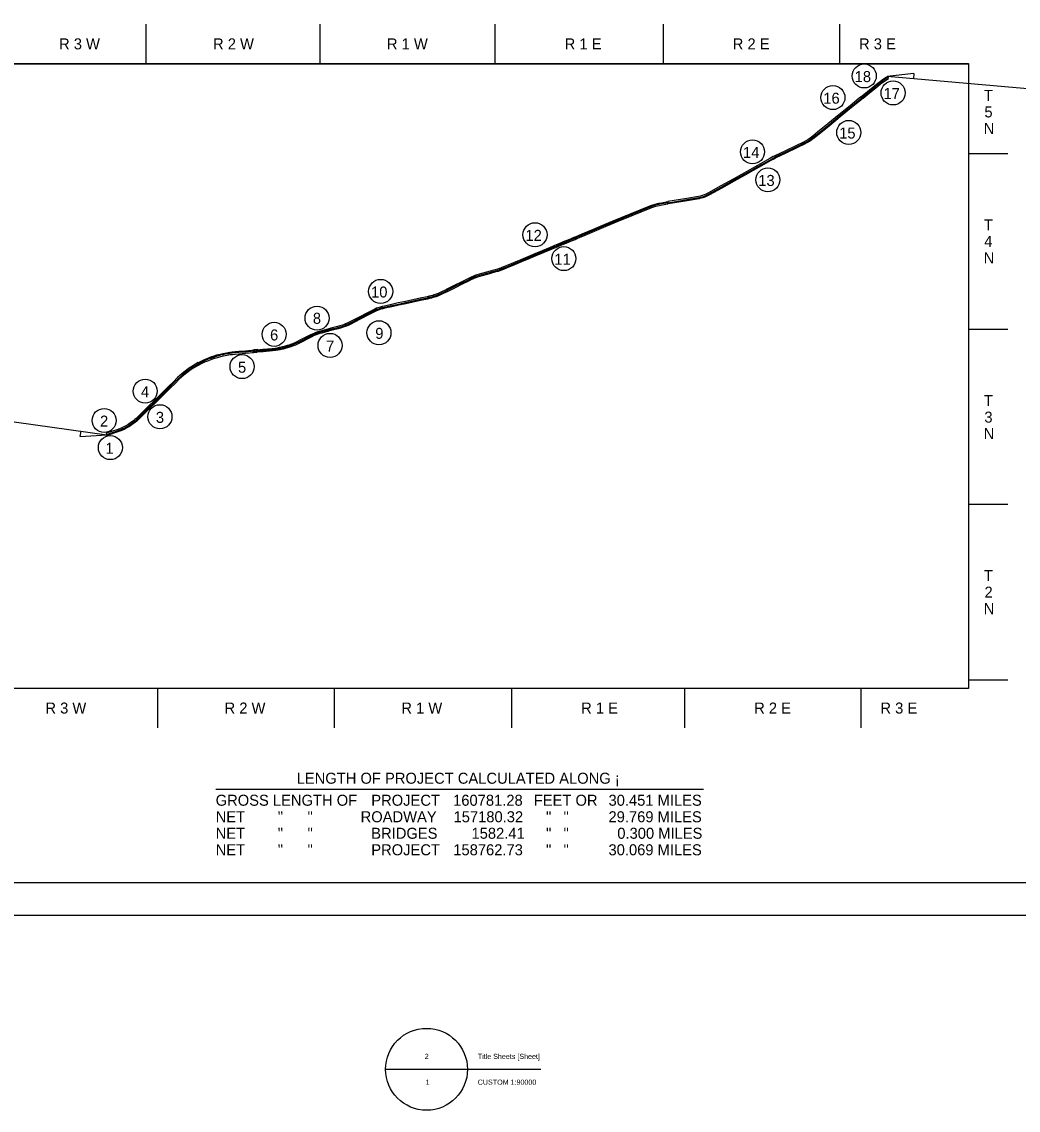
# Model space of a CAD drawing. Extents: x -0.96 to 2.36, y -0.12 to 0.92.
# Drawn here: x 0.451 to 1.084, y -0.124 to 0.568 of the extents above; entities that cross this region are included whole.
import ezdxf

# ---------------------------------------------------------------- set-up
doc = ezdxf.new("R2010")
doc.units = 0
for name, color, linetype in [('Default', 7, 'Continuous'), ('DSN_DRFT_DNC', 7, 'Continuous'), ('Level 41', 7, 'Continuous'), ('Level 57', 7, 'Continuous'), ('SHET_Annotations', 7, 'Continuous'), ('SHET_Border-Lines', 7, 'Continuous'), ('SHET_Border-Text', 7, 'Continuous')]:
    doc.layers.add(name, color=color, linetype=linetype)

msp = doc.modelspace()

# ---------------------------------------------------------------- linework, layer by layer
at = {"layer": 'Default'}
for p, q in [((0.68206, -0.09792), (0.73415, -0.09792)), ((0.70833, -0.09792), (0.78086, -0.09792))]:
    msp.add_line(p, q, dxfattribs=at)
msp.add_circle((0.70811, -0.09792), 0.02604, dxfattribs=at)
at = {"layer": 'DSN_DRFT_DNC'}
msp.add_lwpolyline([(0.4056, 0.54167), (1.05273, 0.54167), (1.05273, 0.1443), (0.4056, 0.1443)], close=True, dxfattribs=at)
at = {"layer": 'Level 41'}
msp.add_lwpolyline([(0.4056, 0.54158), (1.05273, 0.54158), (1.05273, 0.14421), (0.4056, 0.14421)], close=True, dxfattribs=at)
at = {"layer": 'Level 57'}
msp.add_line((0.83298, 0.44301), (0.83297, 0.44301), dxfattribs=at)
for points in [[(0.98504, 0.51997), (0.98418, 0.5203), (0.98863, 0.52394), (0.99421, 0.52849), (0.99591, 0.52987), (0.99871, 0.53192), (1.00046, 0.53302), (1.00124, 0.53346), (1.00164, 0.53276), (1.00087, 0.53233), (0.99916, 0.53125), (0.9964, 0.52923), (0.99472, 0.52787), (0.98913, 0.52332)], [(1.00192, 0.53213), (1.00159, 0.53272), (1.00088, 0.53232), (0.99917, 0.53124), (0.99641, 0.52922), (0.99473, 0.52786), (0.98914, 0.52331), (0.98512, 0.52001), (0.98546, 0.51988), (0.98585, 0.51975), (0.98957, 0.52279), (0.99515, 0.52734), (0.99682, 0.52869), (0.99954, 0.53069), (1.00122, 0.53174)], [(0.96384, 0.50267), (0.9708, 0.50833), (0.97801, 0.51422), (0.98378, 0.51893), (0.98503, 0.51995), (0.98416, 0.52029), (0.98327, 0.51955), (0.9775, 0.51484), (0.97029, 0.50896), (0.96333, 0.50329), (0.95678, 0.49794), (0.9538, 0.49553), (0.95385, 0.49453), (0.95729, 0.49732)], [(0.97081, 0.50832), (0.97802, 0.51421), (0.98379, 0.51892), (0.98498, 0.5199), (0.9857, 0.51962), (0.98421, 0.5184), (0.97844, 0.51369), (0.97123, 0.5078), (0.96427, 0.50214), (0.95772, 0.49679), (0.95463, 0.49429), (0.95394, 0.49379), (0.95391, 0.49459), (0.95423, 0.49482), (0.9573, 0.49731), (0.96385, 0.50266)], [(0.89554, 0.46311), (0.9034, 0.46747), (0.91068, 0.47153), (0.91897, 0.47617), (0.92674, 0.4805), (0.929, 0.48178), (0.92991, 0.48224), (0.93631, 0.48531), (0.94378, 0.48887), (0.94809, 0.49093), (0.9497, 0.49183), (0.95092, 0.49256), (0.9525, 0.4936), (0.95382, 0.49456), (0.95378, 0.49549), (0.95205, 0.49424), (0.9505, 0.49322), (0.94931, 0.49251), (0.94773, 0.49162), (0.94344, 0.48957), (0.93597, 0.48602), (0.92956, 0.48295), (0.92863, 0.48247), (0.92636, 0.48119), (0.91859, 0.47686), (0.91029, 0.47221), (0.90302, 0.46816), (0.89516, 0.46379), (0.88738, 0.45946), (0.88581, 0.45865), (0.88456, 0.45812), (0.88346, 0.45774), (0.88221, 0.4574), (0.88112, 0.45718), (0.87353, 0.45588), (0.8655, 0.45453), (0.86159, 0.45386), (0.86162, 0.45308), (0.86563, 0.45376), (0.87366, 0.45511), (0.88126, 0.45641), (0.88239, 0.45663), (0.88369, 0.45699), (0.88484, 0.45739), (0.88614, 0.45794), (0.88775, 0.45877)], [(0.91101, 0.47092), (0.90374, 0.46687), (0.89588, 0.4625), (0.88808, 0.45816), (0.88644, 0.45731), (0.88509, 0.45674), (0.8839, 0.45633), (0.88255, 0.45596), (0.88138, 0.45573), (0.87377, 0.45443), (0.86574, 0.45307), (0.86171, 0.45239), (0.86168, 0.45306), (0.86563, 0.45373), (0.87366, 0.45509), (0.88126, 0.45639), (0.88239, 0.45661), (0.8837, 0.45696), (0.88485, 0.45737), (0.88615, 0.45791), (0.88776, 0.45875), (0.89555, 0.46308), (0.90342, 0.46745), (0.91069, 0.47151), (0.91899, 0.47615), (0.92675, 0.48048), (0.92901, 0.48176), (0.92992, 0.48222), (0.93632, 0.48529), (0.94379, 0.48884), (0.9481, 0.49091), (0.94971, 0.49181), (0.95093, 0.49254), (0.95251, 0.49358), (0.95377, 0.49449), (0.95379, 0.49368), (0.95289, 0.49303), (0.95129, 0.49197), (0.95004, 0.49123), (0.9484, 0.49031), (0.94407, 0.48824), (0.93661, 0.48469), (0.93022, 0.48162), (0.92933, 0.48117), (0.92708, 0.4799), (0.91931, 0.47557)], [(0.85145, 0.45165), (0.85352, 0.45229), (0.85573, 0.45283), (0.85758, 0.45318), (0.86155, 0.45385), (0.86158, 0.45307), (0.85771, 0.45241), (0.8559, 0.45207), (0.85373, 0.45154), (0.85169, 0.45091), (0.85003, 0.45034), (0.83285, 0.4433), (0.82964, 0.44196), (0.82209, 0.4388), (0.81462, 0.43566), (0.80732, 0.43261), (0.80349, 0.431), (0.80232, 0.43051), (0.80126, 0.43007), (0.80008, 0.42957), (0.79665, 0.42815), (0.79324, 0.42671), (0.79001, 0.42537), (0.7888, 0.42485), (0.78878, 0.42541), (0.78877, 0.42568), (0.78971, 0.42608), (0.79294, 0.42743), (0.79635, 0.42886), (0.79978, 0.43028), (0.80096, 0.43078), (0.80202, 0.43122), (0.80318, 0.43172), (0.80702, 0.43332), (0.81432, 0.43638), (0.82178, 0.43951), (0.82934, 0.44268), (0.83255, 0.44402), (0.83256, 0.44402), (0.84976, 0.45107)], [(0.76368, 0.41436), (0.76824, 0.41627), (0.77283, 0.41819), (0.77728, 0.42006), (0.78197, 0.422), (0.78707, 0.42415), (0.78876, 0.42486), (0.78879, 0.42403), (0.78738, 0.42343), (0.78227, 0.42129), (0.77758, 0.41934), (0.77314, 0.41747), (0.76854, 0.41555), (0.76398, 0.41364), (0.75939, 0.41171), (0.75651, 0.41051), (0.75519, 0.41003), (0.75517, 0.41085), (0.75622, 0.41123), (0.75908, 0.41243)], [(0.76367, 0.41439), (0.76822, 0.4163), (0.77282, 0.41822), (0.77727, 0.42009), (0.78196, 0.42203), (0.78706, 0.42418), (0.7887, 0.42487), (0.78867, 0.42558), (0.78681, 0.42478), (0.78171, 0.42264), (0.77702, 0.42069), (0.77257, 0.41883), (0.76797, 0.41691), (0.76341, 0.41499), (0.75882, 0.41307), (0.75597, 0.41188), (0.7552, 0.4116), (0.75523, 0.41091), (0.75621, 0.41126), (0.75907, 0.41246)], [(0.71121, 0.39248), (0.71006, 0.39219), (0.7088, 0.39191), (0.70433, 0.39093), (0.6997, 0.38993), (0.695, 0.38891), (0.69048, 0.38793), (0.68609, 0.38698), (0.6816, 0.386), (0.6802, 0.38568), (0.67912, 0.3854), (0.67839, 0.38516), (0.67684, 0.38461), (0.67584, 0.38418), (0.67499, 0.38377), (0.67377, 0.38314), (0.67167, 0.38204), (0.66549, 0.37881), (0.66004, 0.37598), (0.65875, 0.37537), (0.65714, 0.37471), (0.65636, 0.3744), (0.65511, 0.37397), (0.65337, 0.37343), (0.65181, 0.37301), (0.64833, 0.37218), (0.64569, 0.37153), (0.64565, 0.37236), (0.64814, 0.37297), (0.65161, 0.3738), (0.65314, 0.37421), (0.65486, 0.37474), (0.65608, 0.37516), (0.65683, 0.37547), (0.65842, 0.37611), (0.65968, 0.37671), (0.66511, 0.37953), (0.67129, 0.38276), (0.6734, 0.38386), (0.67462, 0.3845), (0.6755, 0.38492), (0.67654, 0.38537), (0.67813, 0.38594), (0.6789, 0.38618), (0.68, 0.38647), (0.68142, 0.3868), (0.68592, 0.38778), (0.6903, 0.38873), (0.69483, 0.3897), (0.69953, 0.39073), (0.70415, 0.39172), (0.70862, 0.3927), (0.70987, 0.39298), (0.711, 0.39326), (0.7121, 0.39357), (0.71295, 0.39385), (0.71391, 0.39417), (0.71575, 0.39487), (0.71714, 0.39547), (0.7184, 0.39606), (0.71985, 0.39678), (0.72123, 0.39747), (0.72596, 0.39982), (0.73039, 0.40204), (0.73433, 0.404), (0.73632, 0.40498), (0.73717, 0.40538), (0.73789, 0.4057), (0.73912, 0.4062), (0.74033, 0.40664), (0.74173, 0.40711), (0.74316, 0.40754), (0.74643, 0.4084), (0.74796, 0.4088), (0.752, 0.40988), (0.75336, 0.41027), (0.7545, 0.41063), (0.75514, 0.41086), (0.75517, 0.41001), (0.75477, 0.40986), (0.75359, 0.40949), (0.75221, 0.4091), (0.74817, 0.40802), (0.74663, 0.40761), (0.74338, 0.40675), (0.74197, 0.40633), (0.7406, 0.40587), (0.73941, 0.40544), (0.73821, 0.40495), (0.73751, 0.40464), (0.73668, 0.40425), (0.7347, 0.40327), (0.73076, 0.40131), (0.72632, 0.39909), (0.72159, 0.39675), (0.72021, 0.39605), (0.71876, 0.39533), (0.71748, 0.39473), (0.71606, 0.39411), (0.71418, 0.39341), (0.71321, 0.39308), (0.71233, 0.39279)], [(0.71082, 0.39392), (0.70972, 0.39364), (0.70848, 0.39337), (0.70401, 0.39239), (0.69938, 0.39139), (0.69468, 0.39036), (0.69016, 0.38939), (0.68578, 0.38844), (0.68127, 0.38746), (0.67984, 0.38713), (0.67871, 0.38683), (0.67791, 0.38658), (0.67629, 0.386), (0.67522, 0.38553), (0.67432, 0.3851), (0.67308, 0.38446), (0.67098, 0.38336), (0.6648, 0.38013), (0.65938, 0.37732), (0.65815, 0.37673), (0.65658, 0.37609), (0.65584, 0.3758), (0.65465, 0.37538), (0.65296, 0.37486), (0.65144, 0.37446), (0.64798, 0.37363), (0.64567, 0.37306), (0.64572, 0.37239), (0.64813, 0.37298), (0.65161, 0.37381), (0.65314, 0.37422), (0.65486, 0.37475), (0.65608, 0.37517), (0.65683, 0.37548), (0.65842, 0.37612), (0.65968, 0.37672), (0.66511, 0.37954), (0.67129, 0.38277), (0.67339, 0.38387), (0.67462, 0.38451), (0.6755, 0.38493), (0.67654, 0.38538), (0.67813, 0.38595), (0.6789, 0.38619), (0.68, 0.38648), (0.68142, 0.38681), (0.68592, 0.38779), (0.6903, 0.38874), (0.69482, 0.38971), (0.69952, 0.39074), (0.70415, 0.39173), (0.70862, 0.39271), (0.70987, 0.39299), (0.711, 0.39327), (0.7121, 0.39358), (0.71295, 0.39386), (0.71391, 0.39418), (0.71575, 0.39488), (0.71714, 0.39548), (0.7184, 0.39607), (0.71985, 0.39679), (0.72122, 0.39748), (0.72596, 0.39983), (0.73039, 0.40205), (0.73433, 0.40401), (0.73632, 0.40499), (0.73717, 0.40539), (0.73789, 0.40571), (0.73912, 0.40621), (0.74033, 0.40665), (0.74172, 0.40712), (0.74316, 0.40755), (0.74642, 0.40841), (0.74796, 0.40881), (0.752, 0.40989), (0.75335, 0.41028), (0.7545, 0.41064), (0.75507, 0.41085), (0.75505, 0.41155), (0.75429, 0.41127), (0.75316, 0.41091), (0.75182, 0.41053), (0.74778, 0.40946), (0.74625, 0.40905), (0.74298, 0.40819), (0.74152, 0.40775), (0.7401, 0.40728), (0.73888, 0.40683), (0.73763, 0.40632), (0.73689, 0.406), (0.73603, 0.40559), (0.73403, 0.4046), (0.73009, 0.40264), (0.72566, 0.40043), (0.72093, 0.39808), (0.71955, 0.39738), (0.71811, 0.39667), (0.71686, 0.39608), (0.7155, 0.39549), (0.71368, 0.39481), (0.71274, 0.39449), (0.7119, 0.39422)], [(0.60412, 0.35843), (0.59973, 0.35804), (0.6001, 0.35889), (0.60405, 0.35925), (0.60996, 0.35973), (0.61185, 0.35998), (0.61337, 0.36021), (0.61478, 0.36048), (0.61677, 0.36092), (0.61807, 0.36122), (0.61997, 0.36177), (0.62099, 0.36211), (0.62267, 0.36272), (0.62434, 0.36339), (0.62605, 0.36418), (0.62771, 0.36499), (0.63313, 0.36782), (0.63485, 0.36869), (0.63596, 0.3692), (0.63693, 0.3696), (0.63815, 0.37007), (0.63938, 0.3705), (0.64118, 0.37104), (0.6434, 0.37165), (0.64557, 0.37217), (0.64559, 0.37133), (0.64361, 0.37085), (0.64141, 0.37025), (0.63963, 0.36971), (0.63844, 0.3693), (0.63723, 0.36884), (0.63629, 0.36844), (0.63521, 0.36795), (0.6335, 0.36709), (0.62808, 0.36426), (0.6264, 0.36344), (0.62467, 0.36264), (0.62296, 0.36195), (0.62126, 0.36133), (0.62021, 0.36099), (0.61828, 0.36043), (0.61695, 0.36011), (0.61494, 0.35968), (0.61351, 0.3594), (0.61196, 0.35917), (0.61005, 0.35891)], [(0.59987, 0.3588), (0.60025, 0.35966), (0.60398, 0.35999), (0.60988, 0.36048), (0.61174, 0.36072), (0.61324, 0.36095), (0.61462, 0.36121), (0.6166, 0.36165), (0.61787, 0.36195), (0.61975, 0.36249), (0.62074, 0.36281), (0.6224, 0.36342), (0.62404, 0.36408), (0.62573, 0.36486), (0.62737, 0.36566), (0.63278, 0.36849), (0.63453, 0.36937), (0.63566, 0.36988), (0.63664, 0.37029), (0.63789, 0.37077), (0.63914, 0.37121), (0.64097, 0.37176), (0.64321, 0.37237), (0.64554, 0.37293), (0.64556, 0.3721), (0.64342, 0.37158), (0.6412, 0.37097), (0.6394, 0.37043), (0.63817, 0.37), (0.63695, 0.36953), (0.63599, 0.36913), (0.63488, 0.36863), (0.63316, 0.36776), (0.62774, 0.36493), (0.62608, 0.36412), (0.62437, 0.36333), (0.62269, 0.36265), (0.62101, 0.36204), (0.61999, 0.3617), (0.61808, 0.36116), (0.61678, 0.36085), (0.61479, 0.36041), (0.61338, 0.36014), (0.61185, 0.35991), (0.60997, 0.35966), (0.60405, 0.35917)], [(0.57685, 0.3569), (0.57855, 0.3573), (0.57976, 0.35755), (0.58194, 0.35794), (0.583, 0.3581), (0.58447, 0.35828), (0.58633, 0.35848), (0.58865, 0.35869), (0.59291, 0.35903), (0.59889, 0.35957), (0.5984, 0.3587), (0.59298, 0.35822), (0.58872, 0.35788), (0.58642, 0.35767), (0.58457, 0.35747), (0.58311, 0.35729), (0.58207, 0.35713), (0.57991, 0.35675), (0.57873, 0.3565), (0.57705, 0.35611), (0.57495, 0.35554), (0.57334, 0.35504), (0.57128, 0.35436), (0.56931, 0.3536), (0.56689, 0.35257), (0.56472, 0.35155), (0.563, 0.35062), (0.56299, 0.35155), (0.56435, 0.35228), (0.56656, 0.35332), (0.569, 0.35436), (0.571, 0.35513), (0.57309, 0.35581), (0.57472, 0.35633)], [(0.57704, 0.35617), (0.57493, 0.3556), (0.57332, 0.35509), (0.57126, 0.35441), (0.56928, 0.35365), (0.56686, 0.35263), (0.56469, 0.3516), (0.5632, 0.3508), (0.56301, 0.35069), (0.56302, 0.34978), (0.56359, 0.3501), (0.56506, 0.35088), (0.56719, 0.3519), (0.56959, 0.35291), (0.57153, 0.35366), (0.57356, 0.35433), (0.57516, 0.35483), (0.57723, 0.35539), (0.57889, 0.35577), (0.58005, 0.35602), (0.58219, 0.3564), (0.58321, 0.35655), (0.58465, 0.35673), (0.58649, 0.35693), (0.58878, 0.35714), (0.59304, 0.35748), (0.59826, 0.35794), (0.59862, 0.35878), (0.59298, 0.35828), (0.58871, 0.35794), (0.58641, 0.35773), (0.58456, 0.35753), (0.5831, 0.35735), (0.58206, 0.35719), (0.5799, 0.35681), (0.57872, 0.35656)], [(0.60032, 0.35809), (0.60069, 0.35894), (0.59804, 0.35874), (0.59767, 0.35789)], [(0.60047, 0.35885), (0.60085, 0.35971), (0.59825, 0.35952), (0.59776, 0.35864)], [(0.50443, 0.30652), (0.50466, 0.30583), (0.51149, 0.30809), (0.51411, 0.30908), (0.51589, 0.30989), (0.51719, 0.31059), (0.51873, 0.31153), (0.52052, 0.31272), (0.52244, 0.31415), (0.52313, 0.31471), (0.52384, 0.31532), (0.52795, 0.31939), (0.53899, 0.33023), (0.54477, 0.33602), (0.54761, 0.33877), (0.55034, 0.34142), (0.55174, 0.34274), (0.55324, 0.34405), (0.55509, 0.34555), (0.5571, 0.34703), (0.55914, 0.34838), (0.56163, 0.34991), (0.56296, 0.35064), (0.56295, 0.35148), (0.56127, 0.35054), (0.55875, 0.349), (0.55668, 0.34763), (0.55465, 0.34613), (0.55276, 0.34461), (0.55124, 0.34328), (0.54983, 0.34195), (0.5471, 0.3393), (0.54425, 0.33654), (0.53847, 0.33075), (0.52743, 0.31991), (0.52334, 0.31586), (0.52266, 0.31527), (0.52199, 0.31473), (0.5201, 0.31332), (0.51834, 0.31215), (0.51683, 0.31123), (0.51556, 0.31055), (0.51383, 0.30975), (0.51124, 0.30878)], [(0.50484, 0.30523), (0.50465, 0.30582), (0.51149, 0.30809), (0.51411, 0.30908), (0.51589, 0.30989), (0.51719, 0.31059), (0.51873, 0.31153), (0.52052, 0.31272), (0.52244, 0.31415), (0.52313, 0.31471), (0.52384, 0.31532), (0.52795, 0.31939), (0.53899, 0.33023), (0.54477, 0.33602), (0.54761, 0.33877), (0.55034, 0.34142), (0.55174, 0.34274), (0.55324, 0.34405), (0.55509, 0.34555), (0.5571, 0.34703), (0.55914, 0.34838), (0.56163, 0.34991), (0.56298, 0.35065), (0.56299, 0.34978), (0.56202, 0.34924), (0.55956, 0.34774), (0.55754, 0.3464), (0.55556, 0.34494), (0.55373, 0.34346), (0.55225, 0.34217), (0.55087, 0.34086), (0.54815, 0.33822), (0.54531, 0.33547), (0.53953, 0.32969), (0.52848, 0.31884), (0.52436, 0.31476), (0.52362, 0.31412), (0.52291, 0.31355), (0.52097, 0.31209), (0.51914, 0.31089), (0.51757, 0.30993), (0.51623, 0.3092), (0.5144, 0.30837), (0.51174, 0.30737), (0.50503, 0.30514)]]:
    msp.add_lwpolyline(points, close=True, dxfattribs=at)
for points in [[(0.86132, 0.453), (0.85772, 0.45239), (0.8559, 0.45205), (0.85374, 0.45152), (0.8517, 0.45089), (0.85004, 0.45032), (0.83286, 0.44328)], [(0.83312, 0.44266), (0.85028, 0.44969), (0.85191, 0.45025), (0.85392, 0.45086), (0.85604, 0.45139), (0.85784, 0.45172), (0.86156, 0.45236), (0.86154, 0.45282)], [(0.83286, 0.44328), (0.82965, 0.44194), (0.82209, 0.43878), (0.81463, 0.43564), (0.80733, 0.43259), (0.80349, 0.43098), (0.80233, 0.43048), (0.80127, 0.43005), (0.80009, 0.42954), (0.79666, 0.42812), (0.79325, 0.42669), (0.79002, 0.42535), (0.78885, 0.42485), (0.78886, 0.4244)], [(0.78913, 0.42423), (0.79029, 0.42472), (0.79351, 0.42607), (0.79692, 0.4275), (0.80035, 0.42892), (0.80153, 0.42942), (0.80259, 0.42986), (0.80376, 0.43036), (0.80759, 0.43196), (0.81489, 0.43502), (0.82236, 0.43815), (0.82991, 0.44132), (0.83312, 0.44266)]]:
    msp.add_lwpolyline(points, dxfattribs=at)
at = {"layer": 'SHET_Annotations'}
for p, q in [((0.52967, 0.56667), (0.52967, 0.54167)), ((0.64025, 0.56667), (0.64025, 0.54167)), ((0.75161, 0.56667), (0.75161, 0.54167)), ((0.85848, 0.56667), (0.85848, 0.54167)), ((0.97064, 0.56667), (0.97064, 0.54167)), ((1.01799, 0.53524), (1.00111, 0.53338)), ((1.11673, 0.5232), (1.00111, 0.53338)), ((1.01799, 0.53524), (1.0177, 0.53191)), ((1.05273, 0.4844), (1.07773, 0.4844)), ((1.05273, 0.37267), (1.07773, 0.37267)), ((0.23672, 0.34331), (0.50486, 0.30548)), ((0.4879, 0.3045), (0.48836, 0.30781)), ((0.4879, 0.3045), (0.50486, 0.30548)), ((1.05273, 0.26136), (1.07773, 0.26136)), ((1.05273, 0.14971), (1.07773, 0.14971)), ((0.53699, 0.1443), (0.53699, 0.1193)), ((0.64942, 0.1443), (0.64943, 0.1193)), ((0.76206, 0.1443), (0.76206, 0.1193)), ((0.87212, 0.1443), (0.87212, 0.1193)), ((0.98422, 0.1443), (0.98422, 0.1193))]:
    msp.add_line(p, q, dxfattribs=at)
for centre in [(0.98646, 0.53375), (0.96654, 0.52001), (1.0048, 0.52296), (0.9766, 0.49786), (0.91542, 0.48549), (0.92515, 0.46771), (0.77708, 0.43279), (0.79545, 0.4176), (0.67892, 0.39677), (0.63846, 0.37976), (0.6112, 0.36946), (0.67785, 0.37047), (0.64673, 0.36242), (0.59078, 0.34892), (0.5292, 0.33335), (0.50308, 0.31467), (0.50308, 0.31467), (0.53857, 0.31706), (0.50703, 0.29741), (0.50703, 0.29741)]:
    msp.add_circle(centre, 0.00764, dxfattribs=at)
at = {"layer": 'SHET_Border-Lines'}
for points in [[(0, 0), (1.41666, 0), (1.41666, 0.91666), (0, 0.91666)], [(0.04167, 0.02083), (1.39583, 0.02083), (1.39583, 0.89583), (0.04167, 0.89583)]]:
    msp.add_lwpolyline(points, close=True, dxfattribs=at)
at = {"layer": 'SHET_Border-Text'}
msp.add_line((0.57417, 0.08017), (0.88416, 0.08017), dxfattribs=at)

# ---------------------------------------------------------------- texts
at = {"layer": 'Default'}
for s, height, p in [('2', 0.00328, (0.70695, -0.09135)), ('Title Sheets [Sheet]', 0.0032808, (0.74066, -0.09135)), ('1', 0.00328, (0.70748, -0.10776)), ('CUSTOM 1:90000', 0.0032808, (0.74066, -0.10776))]:
    msp.add_text(s, height=height, dxfattribs=at).set_placement(p)
at = {"layer": 'SHET_Annotations'}
for s, p in [('R 3 W', (0.4744, 0.55067)), ('R 2 W', (0.57233, 0.55067)), ('R 1 W', (0.6829, 0.55067)), ('R 1 E', (0.79594, 0.55067)), ('R 2 E', (0.90282, 0.55067)), ('R 3 E', (0.98314, 0.55067)), ('18', (0.98037, 0.52986)), ('17', (0.99871, 0.51908)), ('16', (0.96045, 0.51612)), ('T', (1.06259, 0.5179)), ('5', (1.06287, 0.5074)), ('15', (0.97051, 0.49397)), ('N', (1.06243, 0.4969)), ('14', (0.90934, 0.48161)), ('13', (0.91907, 0.46382)), ('T', (1.06259, 0.43553)), ('12', (0.77099, 0.4289)), ('4', (1.06273, 0.42503)), ('11', (0.78936, 0.41371)), ('N', (1.06243, 0.41453)), ('10', (0.67283, 0.39288)), ('8', (0.63581, 0.37614)), ('6', (0.60859, 0.36557)), ('9', (0.67549, 0.36658)), ('7', (0.64421, 0.35853)), ('5', (0.5882, 0.34504)), ('4', (0.5265, 0.32946)), ('T', (1.06259, 0.3238)), ('3', (0.53598, 0.31317)), ('3', (1.06284, 0.3133)), ('2', (0.50045, 0.31078)), ('N', (1.06243, 0.3028)), ('1', (0.50391, 0.29352)), ('T', (1.06259, 0.2125)), ('2', (1.06293, 0.202)), ('N', (1.06243, 0.1915)), ('R 3 W', (0.46572, 0.1283)), ('R 2 W', (0.57965, 0.1283)), ('R 1 W', (0.69208, 0.1283)), ('R 1 E', (0.8064, 0.1283)), ('R 2 E', (0.91645, 0.1283)), ('R 3 E', (0.99672, 0.1283)), ('160781.28', (0.72501, 0.06967)), ('30.451 MILES', (0.82382, 0.06967)), ('157180.32', (0.72529, 0.05917)), ('29.769 MILES', (0.82382, 0.05917)), ('1582.41', (0.73669, 0.04867)), ('0.300 MILES', (0.82941, 0.04867)), ('158762.73', (0.72511, 0.03817)), ('30.069 MILES', (0.82382, 0.03817))]:
    msp.add_text(s, height=0.007, dxfattribs=at).set_placement(p)
at = {"layer": 'SHET_Border-Text'}
for s, p in [('LENGTH OF PROJECT CALCULATED ALONG ¡', (0.62551, 0.08367)), ('GROSS LENGTH OF', (0.57399, 0.06967)), ('PROJECT', (0.67296, 0.06967)), ('FEET OR', (0.77631, 0.06967)), ('NET        "      "', (0.57399, 0.05917)), ('ROADWAY', (0.66618, 0.05917)), ('   "   "', (0.77631, 0.05917)), ('NET        "      "', (0.57399, 0.04867)), ('BRIDGES', (0.67293, 0.04867)), ('   "   "', (0.77631, 0.04867)), ('NET        "      "', (0.57399, 0.03817)), ('PROJECT', (0.67296, 0.03817)), ('   "   "', (0.77631, 0.03817))]:
    msp.add_text(s, height=0.007, dxfattribs=at).set_placement(p)

doc.saveas('drawing.dxf')
